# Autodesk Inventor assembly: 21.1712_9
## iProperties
Created: 2007-05
Part Number: 21.1712_9
Document SubType Name: Assembly
Designer: Andy Moles
Mass: 54.9061 g
Surface Area: 63.2689 cm^2
Volume: 6.99139 cm^3
Density: 7.85338 g/cm^3
Description: DOOR CHAIN CLAMP LOW PROF.
Vendor: S
Stock Number: 21.1712
Author: Andy Moles
